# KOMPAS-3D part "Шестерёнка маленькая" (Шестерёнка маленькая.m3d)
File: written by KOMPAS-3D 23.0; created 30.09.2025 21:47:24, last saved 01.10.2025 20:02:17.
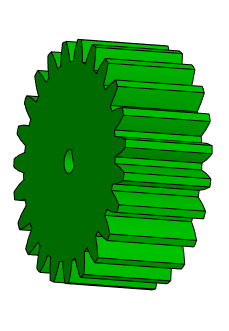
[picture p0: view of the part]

Document properties: Автор: Inspektor_Kot; Полное имя файла: C:\Users\Lost\Desktop\Варианты\Вариант 7\Вариант 7\Шестерёнка маленькая.m3d

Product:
- Part/product: Шестерёнка маленькая
    Масса: 0.256368

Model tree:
1. Операция без истории:1
2. Эскиз:1  (with: Операция без истории:1)
3. Элемент выдавливания:1
     Расстояние 2 = 20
